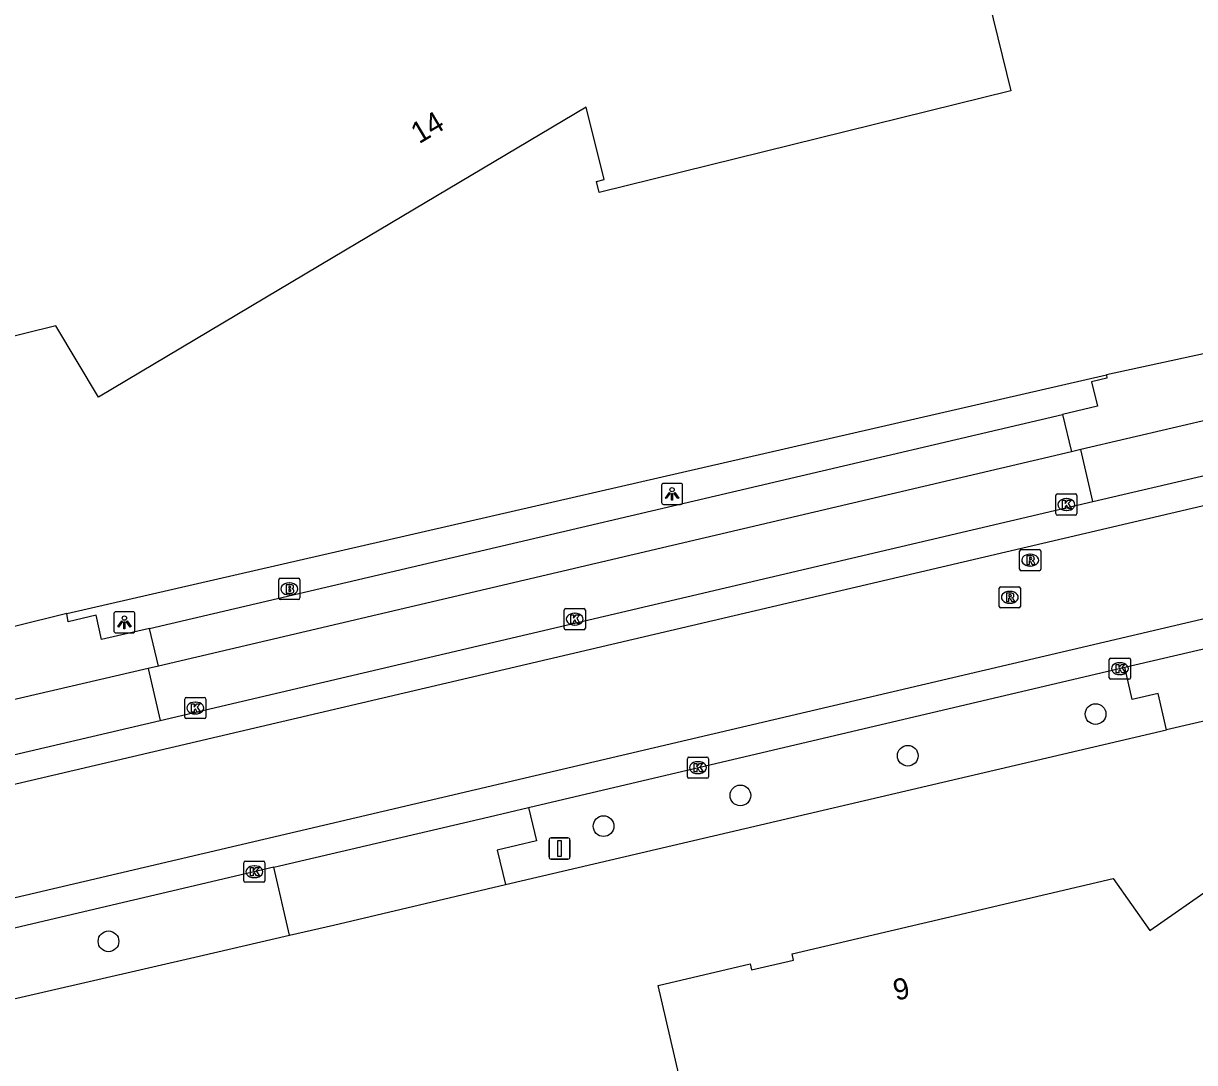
# Model space of a CAD drawing. Extents: x 156651 to 158072, y 387631 to 388990.
# Drawn here: x 157322.6 to 157378, y 388375.7 to 388424.8 of the extents above; entities that cross this region are included whole.
import ezdxf

# ---------------------------------------------------------------- set-up
doc = ezdxf.new("R2010")
doc.units = 0
for name, color, linetype in [('IMGEO_Berm_groen', 7, 'Continuous'), ('IMGEO_Boom', 7, 'Continuous'), ('IMGEO_Brandkraan', 7, 'Continuous'), ('IMGEO_Groenvoorziening', 7, 'Continuous'), ('IMGEO_Hek', 7, 'Continuous'), ('IMGEO_Kolk', 7, 'Continuous'), ('IMGEO_Lichtpunt', 7, 'Continuous'), ('IMGEO_Pand', 7, 'Continuous'), ('IMGEO_Pand_nummerreeks', 7, 'Continuous'), ('IMGEO_Parkeervlak_gesloten', 7, 'Continuous'), ('IMGEO_Rijbaan_lokaal_gesloten', 7, 'Continuous'), ('IMGEO_Rijbaan_lokaal_open', 7, 'Continuous'), ('IMGEO_Rioolput', 7, 'Continuous'), ('IMGEO_Verkeersbordpaal', 7, 'Continuous'), ('IMGEO_Voetpad_open', 7, 'Continuous')]:
    doc.layers.add(name, color=color, linetype=linetype)

msp = doc.modelspace()

# ---------------------------------------------------------------- linework, layer by layer
at = {"layer": 'IMGEO_Berm_groen'}
for points in [[(157345.409, 388384.137), (157376.629, 388391.449)], [(157313.544, 388376.755), (157330.931, 388380.761), (157335.195, 388381.743)]]:
    msp.add_lwpolyline(points, dxfattribs=at)
at = {"layer": 'IMGEO_Boom'}
for centre in [(157373.28, 388392.19), (157364.409, 388390.224), (157356.499, 388388.348), (157350.034, 388386.897), (157326.645, 388381.455)]:
    msp.add_circle(centre, 0.489, dxfattribs=at)
at = {"layer": 'IMGEO_Brandkraan'}
for p, q in [((157334.688, 388397.677), (157334.688, 388398.529)), ((157334.763, 388398.603), (157335.615, 388398.603)), ((157335.176, 388398.383), (157335.201, 388398.383)), ((157335.689, 388398.529), (157335.689, 388397.677)), ((157335.199, 388397.823), (157335.174, 388397.823)), ((157335.615, 388397.603), (157334.763, 388397.603))]:
    msp.add_line(p, q, dxfattribs=at)
for points in [[(157334.688, 388397.677), (157334.688, 388398.529)], [(157334.763, 388398.603), (157335.615, 388398.603)], [(157335.036, 388398.303), (157335.036, 388397.903), (157335.249, 388397.903)], [(157335.267, 388398.303), (157335.036, 388398.303)], [(157335.689, 388398.529), (157335.689, 388397.677)], [(157335.215, 388398.222), (157335.161, 388398.222), (157335.161, 388398.146)], [(157335.161, 388398.146), (157335.214, 388398.146)], [(157335.223, 388398.07), (157335.161, 388398.07), (157335.161, 388397.989)], [(157335.161, 388397.989), (157335.223, 388397.989)], [(157335.615, 388397.603), (157334.763, 388397.603)]]:
    msp.add_lwpolyline(points, dxfattribs=at)
for centre, radius, start, end in [((157334.765, 388398.527), 0.0765, 91.552, 178.448), ((157334.765, 388398.527), 0.0765, 91.552, 178.448), ((157335.271, 388398.158), 0.145, 59.4692, 91.5367), ((157335.613, 388398.527), 0.0765, 1.552, 88.448), ((157335.613, 388398.527), 0.0765, 1.552, 88.448), ((157335.216, 388398.184), 0.0379, 267.8285, 90.9355), ((157335.224, 388398.029), 0.0404, 269.8759, 90.5077), ((157335.255, 388398.154), 0.251, 268.6676, 293.5347), ((157335.296, 388398.205), 0.0922, 285.5137, 58.1501), ((157335.301, 388398.013), 0.105, 301.3115, 78.989), ((157334.765, 388397.679), 0.0765, 181.552, 268.448), ((157334.765, 388397.679), 0.0765, 181.552, 268.448), ((157335.613, 388397.679), 0.0765, 271.552, 358.448), ((157335.613, 388397.679), 0.0765, 271.552, 358.448)]:
    msp.add_arc(centre, radius, start, end, dxfattribs=at)
for centre, major_axis, ratio, start_param, end_param in [((157335.175, 388398.103), (-0.387, 0.002), 0.722429, 4.712389, 7.853982), ((157335.2, 388398.103), (-0.39, 0.002), 0.717154, 1.570796, 4.712389)]:
    msp.add_ellipse(centre, major_axis=major_axis, ratio=ratio, start_param=start_param, end_param=end_param, dxfattribs=at)
at = {"layer": 'IMGEO_Groenvoorziening'}
msp.add_lwpolyline([(157324.683, 388396.936), (157373.801, 388408.213)], dxfattribs=at)
at = {"layer": 'IMGEO_Hek'}
msp.add_lwpolyline([(157324.683, 388396.936), (157373.801, 388408.213)], dxfattribs=at)
at = {"layer": 'IMGEO_Kolk'}
for p, q in [((157371.401, 388401.661), (157371.401, 388402.513)), ((157371.476, 388402.587), (157372.328, 388402.587)), ((157371.889, 388402.367), (157371.914, 388402.367)), ((157372.402, 388402.513), (157372.402, 388401.661)), ((157371.912, 388401.807), (157371.887, 388401.807)), ((157372.328, 388401.587), (157371.476, 388401.587)), ((157348.174, 388396.247), (157348.174, 388397.099)), ((157348.249, 388397.173), (157349.101, 388397.173)), ((157348.662, 388396.953), (157348.687, 388396.953)), ((157349.175, 388397.099), (157349.175, 388396.247)), ((157349.101, 388396.173), (157348.249, 388396.173)), ((157348.685, 388396.393), (157348.66, 388396.393)), ((157373.93, 388393.91), (157373.93, 388394.762)), ((157374.005, 388394.836), (157374.857, 388394.836)), ((157374.418, 388394.616), (157374.443, 388394.616)), ((157374.931, 388394.762), (157374.931, 388393.91)), ((157374.441, 388394.056), (157374.416, 388394.056)), ((157374.857, 388393.836), (157374.005, 388393.836)), ((157330.245, 388392.048), (157330.245, 388392.9)), ((157330.32, 388392.974), (157331.172, 388392.974)), ((157331.246, 388392.9), (157331.246, 388392.048)), ((157330.733, 388392.754), (157330.758, 388392.754)), ((157331.172, 388391.974), (157330.32, 388391.974)), ((157330.756, 388392.194), (157330.731, 388392.194)), ((157353.994, 388389.231), (157353.994, 388390.083)), ((157354.069, 388390.157), (157354.921, 388390.157)), ((157354.995, 388390.083), (157354.995, 388389.231)), ((157354.482, 388389.937), (157354.507, 388389.937)), ((157354.921, 388389.157), (157354.069, 388389.157)), ((157354.505, 388389.377), (157354.48, 388389.377)), ((157333.037, 388384.317), (157333.037, 388385.169)), ((157333.112, 388385.243), (157333.964, 388385.243)), ((157333.525, 388385.023), (157333.55, 388385.023)), ((157334.038, 388385.169), (157334.038, 388384.317)), ((157333.548, 388384.463), (157333.523, 388384.463)), ((157333.964, 388384.243), (157333.112, 388384.243))]:
    msp.add_line(p, q, dxfattribs=at)
for points in [[(157371.401, 388401.661), (157371.401, 388402.513)], [(157371.476, 388402.587), (157372.328, 388402.587)], [(157371.722, 388402.287), (157371.845, 388402.287), (157371.845, 388402.136), (157371.975, 388402.287), (157372.139, 388402.287), (157371.993, 388402.136), (157372.146, 388401.887), (157371.994, 388401.887), (157371.909, 388402.051), (157371.845, 388401.984), (157371.845, 388401.887), (157371.722, 388401.887), (157371.722, 388402.287)], [(157372.402, 388402.513), (157372.402, 388401.661)], [(157372.328, 388401.587), (157371.476, 388401.587)], [(157348.174, 388396.247), (157348.174, 388397.099)], [(157348.249, 388397.173), (157349.101, 388397.173)], [(157348.495, 388396.873), (157348.618, 388396.873), (157348.618, 388396.722), (157348.748, 388396.873), (157348.912, 388396.873), (157348.766, 388396.722), (157348.919, 388396.473), (157348.767, 388396.473), (157348.682, 388396.637), (157348.618, 388396.57), (157348.618, 388396.473), (157348.495, 388396.473), (157348.495, 388396.873)], [(157349.175, 388397.099), (157349.175, 388396.247)], [(157349.101, 388396.173), (157348.249, 388396.173)], [(157373.93, 388393.91), (157373.93, 388394.762)], [(157374.005, 388394.836), (157374.857, 388394.836)], [(157374.251, 388394.536), (157374.374, 388394.536), (157374.374, 388394.385), (157374.504, 388394.536), (157374.668, 388394.536), (157374.522, 388394.385), (157374.675, 388394.136), (157374.523, 388394.136), (157374.438, 388394.3), (157374.374, 388394.233), (157374.374, 388394.136), (157374.251, 388394.136), (157374.251, 388394.536)], [(157374.931, 388394.762), (157374.931, 388393.91)], [(157374.857, 388393.836), (157374.005, 388393.836)], [(157330.245, 388392.048), (157330.245, 388392.9)], [(157330.32, 388392.974), (157331.172, 388392.974)], [(157331.246, 388392.9), (157331.246, 388392.048)], [(157330.566, 388392.674), (157330.689, 388392.674), (157330.689, 388392.523), (157330.819, 388392.674), (157330.983, 388392.674), (157330.837, 388392.523), (157330.99, 388392.274), (157330.838, 388392.274), (157330.753, 388392.438), (157330.689, 388392.371), (157330.689, 388392.274), (157330.566, 388392.274), (157330.566, 388392.674)], [(157331.172, 388391.974), (157330.32, 388391.974)], [(157353.994, 388389.231), (157353.994, 388390.083)], [(157354.069, 388390.157), (157354.921, 388390.157)], [(157354.995, 388390.083), (157354.995, 388389.231)], [(157354.315, 388389.857), (157354.438, 388389.857), (157354.438, 388389.706), (157354.568, 388389.857), (157354.732, 388389.857), (157354.586, 388389.706), (157354.739, 388389.457), (157354.587, 388389.457), (157354.502, 388389.621), (157354.438, 388389.554), (157354.438, 388389.457), (157354.315, 388389.457), (157354.315, 388389.857)], [(157354.921, 388389.157), (157354.069, 388389.157)], [(157333.037, 388384.317), (157333.037, 388385.169)], [(157333.112, 388385.243), (157333.964, 388385.243)], [(157334.038, 388385.169), (157334.038, 388384.317)], [(157333.358, 388384.943), (157333.481, 388384.943), (157333.481, 388384.792), (157333.611, 388384.943), (157333.775, 388384.943), (157333.629, 388384.792), (157333.782, 388384.543), (157333.63, 388384.543), (157333.545, 388384.707), (157333.481, 388384.64), (157333.481, 388384.543), (157333.358, 388384.543), (157333.358, 388384.943)], [(157333.964, 388384.243), (157333.112, 388384.243)]]:
    msp.add_lwpolyline(points, dxfattribs=at)
for centre, start, end in [((157371.478, 388402.511), 91.552, 178.448), ((157371.478, 388402.511), 91.552, 178.448), ((157372.326, 388402.511), 1.552, 88.448), ((157372.326, 388402.511), 1.552, 88.448), ((157371.478, 388401.663), 181.552, 268.448), ((157371.478, 388401.663), 181.552, 268.448), ((157372.326, 388401.663), 271.552, 358.448), ((157372.326, 388401.663), 271.552, 358.448), ((157348.251, 388397.097), 91.552, 178.448), ((157348.251, 388397.097), 91.552, 178.448), ((157349.099, 388397.097), 1.552, 88.448), ((157349.099, 388397.097), 1.552, 88.448), ((157348.251, 388396.249), 181.552, 268.448), ((157348.251, 388396.249), 181.552, 268.448), ((157349.099, 388396.249), 271.552, 358.448), ((157349.099, 388396.249), 271.552, 358.448), ((157374.007, 388394.76), 91.552, 178.448), ((157374.007, 388394.76), 91.552, 178.448), ((157374.855, 388394.76), 1.552, 88.448), ((157374.855, 388394.76), 1.552, 88.448), ((157374.007, 388393.912), 181.552, 268.448), ((157374.007, 388393.912), 181.552, 268.448), ((157374.855, 388393.912), 271.552, 358.448), ((157374.855, 388393.912), 271.552, 358.448), ((157330.322, 388392.898), 91.552, 178.448), ((157330.322, 388392.898), 91.552, 178.448), ((157331.17, 388392.898), 1.552, 88.448), ((157331.17, 388392.898), 1.552, 88.448), ((157330.322, 388392.05), 181.552, 268.448), ((157330.322, 388392.05), 181.552, 268.448), ((157331.17, 388392.05), 271.552, 358.448), ((157331.17, 388392.05), 271.552, 358.448), ((157354.071, 388390.081), 91.552, 178.448), ((157354.071, 388390.081), 91.552, 178.448), ((157354.919, 388390.081), 1.552, 88.448), ((157354.919, 388390.081), 1.552, 88.448), ((157354.071, 388389.233), 181.552, 268.448), ((157354.071, 388389.233), 181.552, 268.448), ((157354.919, 388389.233), 271.552, 358.448), ((157354.919, 388389.233), 271.552, 358.448), ((157333.114, 388385.167), 91.552, 178.448), ((157333.114, 388385.167), 91.552, 178.448), ((157333.962, 388385.167), 1.552, 88.448), ((157333.962, 388385.167), 1.552, 88.448), ((157333.114, 388384.319), 181.552, 268.448), ((157333.114, 388384.319), 181.552, 268.448), ((157333.962, 388384.319), 271.552, 358.448), ((157333.962, 388384.319), 271.552, 358.448)]:
    msp.add_arc(centre, 0.0765, start, end, dxfattribs=at)
for centre, major_axis, ratio, start_param, end_param in [((157371.888, 388402.087), (-0.387, 0.002), 0.722429, 4.712389, 7.853982), ((157371.913, 388402.087), (-0.39, 0.002), 0.717154, 1.570796, 4.712389), ((157348.661, 388396.673), (-0.387, 0.002), 0.722429, 4.712389, 7.853982), ((157348.686, 388396.673), (-0.39, 0.002), 0.717154, 1.570796, 4.712389), ((157374.417, 388394.336), (-0.387, 0.002), 0.722429, 4.712389, 7.853982), ((157374.442, 388394.336), (-0.39, 0.002), 0.717154, 1.570796, 4.712389), ((157330.732, 388392.474), (-0.387, 0.002), 0.722429, 4.712389, 7.853982), ((157330.757, 388392.474), (-0.39, 0.002), 0.717154, 1.570796, 4.712389), ((157354.481, 388389.657), (-0.387, 0.002), 0.722429, 4.712389, 7.853982), ((157354.506, 388389.657), (-0.39, 0.002), 0.717154, 1.570796, 4.712389), ((157333.524, 388384.743), (-0.387, 0.002), 0.722429, 4.712389, 7.853982), ((157333.549, 388384.743), (-0.39, 0.002), 0.717154, 1.570796, 4.712389)]:
    msp.add_ellipse(centre, major_axis=major_axis, ratio=ratio, start_param=start_param, end_param=end_param, dxfattribs=at)
at = {"layer": 'IMGEO_Lichtpunt'}
for p, q in [((157352.774, 388402.993), (157352.774, 388402.186)), ((157352.774, 388402.993), (157352.774, 388402.186)), ((157353.676, 388403.088), (157352.868, 388403.088)), ((157353.676, 388403.088), (157352.868, 388403.088)), ((157353.77, 388402.186), (157353.77, 388402.993)), ((157353.77, 388402.186), (157353.77, 388402.993)), ((157352.868, 388402.092), (157353.676, 388402.092)), ((157352.868, 388402.092), (157353.676, 388402.092)), ((157326.898, 388396.927), (157326.898, 388396.12)), ((157326.898, 388396.927), (157326.898, 388396.12)), ((157327.8, 388397.022), (157326.992, 388397.022)), ((157327.8, 388397.022), (157326.992, 388397.022)), ((157327.894, 388396.12), (157327.894, 388396.927)), ((157327.894, 388396.12), (157327.894, 388396.927)), ((157326.992, 388396.026), (157327.8, 388396.026)), ((157326.992, 388396.026), (157327.8, 388396.026))]:
    msp.add_line(p, q, dxfattribs=at)
for points in [[(157353.148, 388402.657), (157353.187, 388402.629), (157352.999, 388402.367), (157352.961, 388402.394), (157353.148, 388402.657)], [(157353.25, 388402.609), (157353.297, 388402.609), (157353.297, 388402.287), (157353.25, 388402.287), (157353.25, 388402.609)], [(157353.36, 388402.629), (157353.398, 388402.656), (157353.585, 388402.394), (157353.546, 388402.366), (157353.36, 388402.629)], [(157327.272, 388396.591), (157327.311, 388396.563), (157327.123, 388396.301), (157327.085, 388396.328), (157327.272, 388396.591)], [(157327.374, 388396.543), (157327.421, 388396.543), (157327.421, 388396.221), (157327.374, 388396.221), (157327.374, 388396.543)], [(157327.484, 388396.563), (157327.522, 388396.59), (157327.709, 388396.328), (157327.67, 388396.3), (157327.484, 388396.563)]]:
    msp.add_lwpolyline(points, dxfattribs=at)
for centre in [(157353.273, 388402.791), (157327.397, 388396.725)]:
    msp.add_circle(centre, 0.0994, dxfattribs=at)
for centre, start, end in [((157352.868, 388402.993), 90, 180), ((157352.868, 388402.993), 90, 180), ((157353.676, 388402.993), 0, 90), ((157353.676, 388402.993), 0, 90), ((157352.868, 388402.186), 180, 270), ((157352.868, 388402.186), 180, 270), ((157353.676, 388402.186), 270, 0), ((157353.676, 388402.186), 270, 360), ((157326.992, 388396.927), 90, 180), ((157326.992, 388396.927), 90, 180), ((157327.8, 388396.927), 0, 90), ((157327.8, 388396.927), 0, 90), ((157326.992, 388396.12), 180, 270), ((157326.992, 388396.12), 180, 270), ((157327.8, 388396.12), 270, 0), ((157327.8, 388396.12), 270, 360)]:
    msp.add_arc(centre, 0.0946, start, end, dxfattribs=at)
at = {"layer": 'IMGEO_Pand'}
for points in [[(157284.502, 388456.96), (157334.322, 388486.665), (157355.907, 388450.522), (157361.576, 388441.009), (157359.3, 388439.653), (157363.908, 388431.969), (157366.579, 388432.623), (157369.271, 388421.635), (157349.824, 388416.833), (157349.697, 388417.348), (157350.066, 388417.439), (157349.219, 388420.866), (157337.253, 388413.756), (157326.165, 388407.167), (157324.155, 388410.534), (157319.806, 388409.455), (157318.426, 388415.265), (157312.35, 388411.637), (157311.791, 388411.303), (157284.502, 388456.96)], [(157380.713, 388318.287), (157352.074, 388359.255), (157349.21, 388363.352), (157355.345, 388367.641), (157352.62, 388379.374), (157356.955, 388380.394), (157357.023, 388380.102), (157359.012, 388380.569), (157358.942, 388380.866), (157374.117, 388384.425), (157375.84, 388381.96), (157381.979, 388386.251), (157382.193, 388385.945), (157384.843, 388382.154), (157413.478, 388341.192), (157414.297, 388341.764), (157419.871, 388333.791), (157386.287, 388310.313), (157380.713, 388318.287)]]:
    msp.add_lwpolyline(points, dxfattribs=at)
at = {"layer": 'IMGEO_Parkeervlak_gesloten'}
for points in [[(157346.492, 388387.772), (157374.667, 388394.404)], [(157334.453, 388384.963), (157314.28, 388380.221)]]:
    msp.add_lwpolyline(points, dxfattribs=at)
at = {"layer": 'IMGEO_Rijbaan_lokaal_gesloten'}
for points in [[(157427.649, 388413.564), (157313.182, 388386.746), (157307.564, 388385.322), (157304.11, 388384.347), (157298.594, 388382.628), (157295.094, 388381.431), (157289.829, 388379.374), (157285.802, 388377.632), (157280.387, 388375.114), (157169.957, 388319.498), (157169.378, 388320.773)], [(157171.244, 388314.319), (157180.605, 388319.095), (157279.127, 388368.703), (157285.498, 388371.81), (157294.645, 388375.709), (157303.766, 388378.867), (157314.242, 388381.65), (157428.83, 388408.527)], [(157373.157, 388402.226), (157383.948, 388404.756)], [(157329.09, 388391.893), (157373.157, 388402.226)], [(157315.455, 388388.699), (157315.678, 388388.748), (157329.09, 388391.893)]]:
    msp.add_lwpolyline(points, dxfattribs=at)
at = {"layer": 'IMGEO_Rijbaan_lokaal_open'}
for points in [[(157374.667, 388394.404), (157388.393, 388397.603)], [(157376.629, 388391.449), (157376.238, 388393.164), (157375.002, 388392.872), (157374.667, 388394.404)], [(157387.909, 388394.064), (157376.629, 388391.449)]]:
    msp.add_lwpolyline(points, dxfattribs=at)
at = {"layer": 'IMGEO_Rioolput'}
for p, q in [((157369.767, 388399.961), (157370.619, 388399.961)), ((157369.692, 388399.035), (157369.692, 388399.887)), ((157370.18, 388399.741), (157370.205, 388399.741)), ((157370.693, 388399.887), (157370.693, 388399.035)), ((157370.619, 388398.961), (157369.767, 388398.961)), ((157370.203, 388399.181), (157370.178, 388399.181)), ((157368.729, 388397.279), (157368.729, 388398.131)), ((157368.804, 388398.205), (157369.656, 388398.205)), ((157369.217, 388397.985), (157369.242, 388397.985)), ((157369.73, 388398.131), (157369.73, 388397.279)), ((157369.656, 388397.205), (157368.804, 388397.205)), ((157369.24, 388397.425), (157369.215, 388397.425))]:
    msp.add_line(p, q, dxfattribs=at)
for points in [[(157369.767, 388399.961), (157370.619, 388399.961)], [(157369.692, 388399.035), (157369.692, 388399.887)], [(157370.281, 388399.659), (157370.029, 388399.661), (157370.029, 388399.261)], [(157370.029, 388399.261), (157370.153, 388399.261), (157370.153, 388399.423), (157370.164, 388399.423)], [(157370.207, 388399.58), (157370.153, 388399.58), (157370.153, 388399.499)], [(157370.153, 388399.499), (157370.205, 388399.499)], [(157370.693, 388399.887), (157370.693, 388399.035)], [(157370.619, 388398.961), (157369.767, 388398.961)], [(157370.211, 388399.394), (157370.282, 388399.261), (157370.422, 388399.261), (157370.357, 388399.387)], [(157368.729, 388397.279), (157368.729, 388398.131)], [(157368.804, 388398.205), (157369.656, 388398.205)], [(157369.318, 388397.903), (157369.066, 388397.905), (157369.066, 388397.505)], [(157369.244, 388397.824), (157369.19, 388397.824), (157369.19, 388397.743)], [(157369.19, 388397.743), (157369.242, 388397.743)], [(157369.73, 388398.131), (157369.73, 388397.279)], [(157369.656, 388397.205), (157368.804, 388397.205)], [(157369.066, 388397.505), (157369.19, 388397.505), (157369.19, 388397.667), (157369.201, 388397.667)], [(157369.248, 388397.638), (157369.319, 388397.505), (157369.459, 388397.505), (157369.394, 388397.631)]]:
    msp.add_lwpolyline(points, dxfattribs=at)
for centre, radius, start, end in [((157369.769, 388399.885), 0.0765, 91.552, 178.448), ((157369.769, 388399.885), 0.0765, 91.552, 178.448), ((157370.617, 388399.885), 0.0765, 1.552, 88.448), ((157370.617, 388399.885), 0.0765, 1.552, 88.448), ((157370.163, 388399.37), 0.0533, 26.0293, 88.6989), ((157370.189, 388399.688), 0.19, 274.7715, 282.9687), ((157370.213, 388399.484), 0.0964, 77.0061, 93.1865), ((157370.227, 388399.541), 0.0378, 276.6634, 79.6772), ((157370.28, 388399.549), 0.109, 350.3612, 89.416), ((157370.278, 388399.549), 0.112, 277.5842, 350.9817), ((157370.262, 388399.334), 0.108, 29.5134, 73.7905), ((157369.769, 388399.037), 0.0765, 181.552, 268.448), ((157369.769, 388399.037), 0.0765, 181.552, 268.448), ((157370.617, 388399.037), 0.0765, 271.552, 358.448), ((157370.617, 388399.037), 0.0765, 271.552, 358.448), ((157368.806, 388398.129), 0.0765, 91.552, 178.448), ((157368.806, 388398.129), 0.0765, 91.552, 178.448), ((157369.226, 388397.932), 0.19, 274.7715, 282.9687), ((157369.25, 388397.728), 0.0964, 77.0061, 93.1865), ((157369.264, 388397.785), 0.0378, 276.6634, 79.6772), ((157369.317, 388397.793), 0.109, 350.3612, 89.416), ((157369.315, 388397.793), 0.112, 277.5842, 350.9817), ((157369.654, 388398.129), 0.0765, 1.552, 88.448), ((157369.654, 388398.129), 0.0765, 1.552, 88.448), ((157368.806, 388397.281), 0.0765, 181.552, 268.448), ((157368.806, 388397.281), 0.0765, 181.552, 268.448), ((157369.2, 388397.614), 0.0533, 26.0293, 88.6989), ((157369.299, 388397.578), 0.108, 29.5134, 73.7905), ((157369.654, 388397.281), 0.0765, 271.552, 358.448), ((157369.654, 388397.281), 0.0765, 271.552, 358.448)]:
    msp.add_arc(centre, radius, start, end, dxfattribs=at)
for centre, major_axis, ratio, start_param, end_param in [((157370.179, 388399.461), (-0.387, 0.002), 0.722429, 4.712389, 7.853982), ((157370.204, 388399.461), (-0.39, 0.002), 0.717154, 1.570796, 4.712389), ((157369.216, 388397.705), (-0.387, 0.002), 0.722429, 4.712389, 7.853982), ((157369.241, 388397.705), (-0.39, 0.002), 0.717154, 1.570796, 4.712389)]:
    msp.add_ellipse(centre, major_axis=major_axis, ratio=ratio, start_param=start_param, end_param=end_param, dxfattribs=at)
at = {"layer": 'IMGEO_Verkeersbordpaal'}
for p, q in [((157347.458, 388385.442), (157347.458, 388386.242)), ((157347.458, 388386.242), (157347.458, 388385.442)), ((157347.558, 388386.342), (157348.348, 388386.342)), ((157348.348, 388386.342), (157347.558, 388386.342)), ((157348.448, 388386.242), (157348.448, 388385.442)), ((157348.448, 388385.442), (157348.448, 388386.242)), ((157348.348, 388385.342), (157347.558, 388385.342)), ((157347.558, 388385.342), (157348.348, 388385.342))]:
    msp.add_line(p, q, dxfattribs=at)
msp.add_lwpolyline([(157347.878, 388386.217), (157348.028, 388386.217), (157348.028, 388385.467), (157347.878, 388385.467), (157347.878, 388386.217)], dxfattribs=at)
for centre, start, end in [((157347.558, 388386.242), 90, 180), ((157347.558, 388386.242), 90, 180), ((157348.348, 388386.242), 0, 90), ((157348.348, 388386.242), 360, 90), ((157347.558, 388385.442), 180, 270), ((157347.558, 388385.442), 180, 270), ((157348.348, 388385.442), 270, 0), ((157348.348, 388385.442), 270, 0)]:
    msp.add_arc(centre, 0.1, start, end, dxfattribs=at)
at = {"layer": 'IMGEO_Voetpad_open'}
for points in [[(157380.626, 388409.68), (157379.563, 388409.386), (157379.547, 388409.463), (157373.801, 388408.213)], [(157373.801, 388408.213), (157373.82, 388408.065), (157373.09, 388407.888), (157373.37, 388406.738), (157371.716, 388406.339)], [(157383.373, 388407.209), (157372.58, 388404.681)], [(157328.59, 388396.232), (157371.716, 388406.339)], [(157371.716, 388406.339), (157372.14, 388404.578)], [(157372.14, 388404.578), (157329.006, 388394.453)], [(157372.58, 388404.681), (157372.14, 388404.578)], [(157373.157, 388402.226), (157372.58, 388404.681)], [(157324.683, 388396.936), (157317.179, 388395.086)], [(157328.59, 388396.232), (157326.321, 388395.709), (157326.061, 388396.855), (157324.745, 388396.549), (157324.683, 388396.936)], [(157329.006, 388394.453), (157328.59, 388396.232)], [(157329.006, 388394.453), (157328.516, 388394.339)], [(157328.516, 388394.339), (157315.086, 388391.22)], [(157328.516, 388394.339), (157329.09, 388391.893)], [(157334.453, 388384.963), (157334.724, 388385.027), (157344.63, 388387.338), (157346.492, 388387.772)], [(157346.492, 388387.772), (157346.86, 388386.208), (157345.015, 388385.758), (157345.409, 388384.137)], [(157335.195, 388381.743), (157334.453, 388384.963)], [(157335.195, 388381.743), (157337.271, 388382.221), (157345.409, 388384.137)]]:
    msp.add_lwpolyline(points, dxfattribs=at)

# ---------------------------------------------------------------- texts
at = {"layer": 'IMGEO_Pand_nummerreeks'}
for s, rotation, p in [('14', 30.7202, (157341.317, 388419.102)), ('9', 13.2239, (157363.851, 388378.643))]:
    msp.add_text(s, height=1, rotation=rotation, dxfattribs=at).set_placement(p)

doc.saveas('drawing.dxf')
